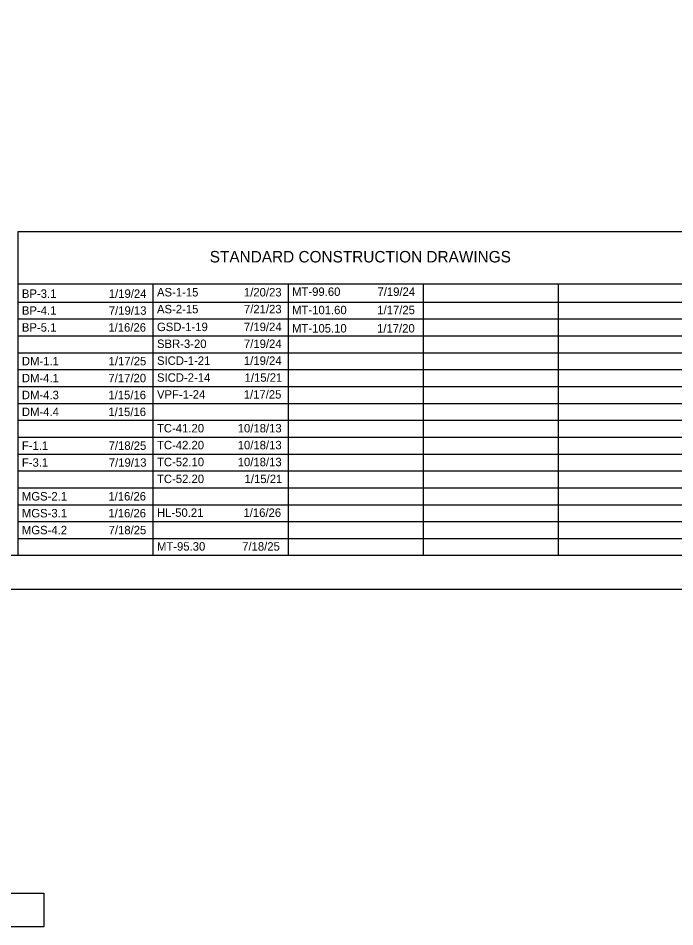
# Model space of a CAD drawing. Extents: x 0 to 34, y -5 to 22.
# Drawn here: x 10.15 to 19.87, y -5 to 8.45 of the extents above; entities that cross this region are included whole.
import ezdxf

# ---------------------------------------------------------------- set-up
doc = ezdxf.new("R2010")
doc.units = 0
for name, color, linetype in [('SH_Border', 7, 'Continuous'), ('SH_Cut_Line', 7, 'Continuous'), ('SH_Data', 7, 'Continuous'), ('SH_Text', 7, 'Continuous')]:
    doc.layers.add(name, color=color, linetype=linetype)

msp = doc.modelspace()

# ---------------------------------------------------------------- linework, layer by layer
at = {"layer": 'SH_Border'}
msp.add_lwpolyline([(1.5, 21.5), (33.5, 21.5), (33.5, 0.5), (1.5, 0.5)], close=True, dxfattribs=at)
at = {"layer": 'SH_Cut_Line'}
msp.add_lwpolyline([(0, 0), (34, 0), (34, 22), (0, 22)], close=True, dxfattribs=at)
at = {"layer": 'SH_Data'}
for p, q in [((10.15, 5.292), (23.6, 5.292)), ((10.15, 0.5), (10.15, 5.292)), ((10.15, 4.521), (23.6, 4.521)), ((12.15, 0.5), (12.15, 4.521)), ((14.15, 0.5), (14.15, 4.521)), ((16.15, 0.5), (16.15, 4.521)), ((18.15, 0.5), (18.15, 4.521)), ((10.15, 4.25), (21.875, 4.25)), ((10.15, 4), (23.6, 4)), ((10.15, 3.75), (23.6, 3.75)), ((10.15, 3.5), (23.6, 3.5)), ((10.15, 3.25), (23.6, 3.25)), ((10.15, 3), (23.6, 3)), ((10.15, 2.75), (23.6, 2.75)), ((10.15, 2.5), (23.6, 2.5)), ((10.15, 2.25), (23.6, 2.25)), ((10.15, 2), (23.6, 2)), ((10.15, 1.75), (23.6, 1.75)), ((10.15, 1.5), (23.6, 1.5)), ((10.15, 1.25), (23.6, 1.25)), ((10.15, 1), (23.6, 1)), ((10.15, 0.75), (23.6, 0.75))]:
    msp.add_line(p, q, dxfattribs=at)
msp.add_lwpolyline([(7.732, -4.999), (7.732, -4.499), (10.532, -4.499), (10.532, -4.999)], close=True, dxfattribs=at)

# ---------------------------------------------------------------- texts
at = {"layer": 'SH_Text'}
for s, height, p in [('STANDARD CONSTRUCTION DRAWINGS', 0.17, (12.986, 4.836)), ('BP-3.1', 0.125, (10.205, 4.312)), ('1/19/24', 0.125, (11.492, 4.312)), ('AS-1-15', 0.125, (12.205, 4.333)), ('1/20/23', 0.125, (13.492, 4.333)), ('MT-99.60', 0.125, (14.205, 4.341)), ('7/19/24', 0.125, (15.469, 4.341)), ('BP-4.1', 0.125, (10.205, 4.062)), ('7/19/13', 0.125, (11.492, 4.062)), ('AS-2-15', 0.125, (12.205, 4.083)), ('7/21/23', 0.125, (13.492, 4.083)), ('MT-101.60', 0.125, (14.205, 4.07)), ('1/17/25', 0.125, (15.466, 4.07)), ('BP-5.1', 0.125, (10.205, 3.812)), ('1/16/26', 0.125, (11.485, 3.812)), ('GSD-1-19', 0.125, (12.205, 3.82)), ('7/19/24', 0.125, (13.492, 3.82)), ('MT-105.10', 0.125, (14.205, 3.799)), ('1/17/20', 0.125, (15.463, 3.799)), ('SBR-3-20', 0.125, (12.205, 3.57)), ('7/19/24', 0.125, (13.492, 3.57)), ('DM-1.1', 0.125, (10.205, 3.313)), ('1/17/25', 0.125, (11.489, 3.313)), ('SICD-1-21', 0.125, (12.205, 3.32)), ('1/19/24', 0.125, (13.492, 3.32)), ('DM-4.1', 0.125, (10.205, 3.062)), ('7/17/20', 0.125, (11.486, 3.062)), ('SICD-2-14', 0.125, (12.205, 3.07)), ('1/15/21', 0.125, (13.502, 3.07)), ('DM-4.3', 0.125, (10.205, 2.812)), ('1/15/16', 0.125, (11.485, 2.812)), ('VPF-1-24', 0.125, (12.205, 2.82)), ('1/17/25', 0.125, (13.489, 2.82)), ('1/15/16', 0.125, (11.485, 2.562)), ('DM-4.4', 0.125, (10.205, 2.562)), ('TC-41.20', 0.125, (12.205, 2.32)), ('10/18/13', 0.125, (13.4, 2.32)), ('F-1.1', 0.125, (10.205, 2.062)), ('7/18/25', 0.125, (11.489, 2.062)), ('TC-42.20', 0.125, (12.205, 2.07)), ('10/18/13', 0.125, (13.4, 2.07)), ('F-3.1', 0.125, (10.205, 1.812)), ('7/19/13', 0.125, (11.492, 1.812)), ('TC-52.10', 0.125, (12.205, 1.82)), ('10/18/13', 0.125, (13.4, 1.82)), ('TC-52.20', 0.125, (12.205, 1.57)), ('1/15/21', 0.125, (13.502, 1.57)), ('MGS-2.1', 0.125, (10.205, 1.312)), ('1/16/26', 0.125, (11.485, 1.312)), ('MGS-3.1', 0.125, (10.205, 1.062)), ('1/16/26', 0.125, (11.485, 1.062)), ('HL-50.21', 0.125, (12.205, 1.07)), ('1/16/26', 0.125, (13.485, 1.07)), ('7/18/25', 0.125, (11.489, 0.812)), ('MGS-4.2', 0.125, (10.205, 0.812)), ('MT-95.30', 0.125, (12.205, 0.57)), ('7/18/25', 0.125, (13.466, 0.57))]:
    msp.add_text(s, height=height, dxfattribs=at).set_placement(p)

doc.saveas('drawing.dxf')
